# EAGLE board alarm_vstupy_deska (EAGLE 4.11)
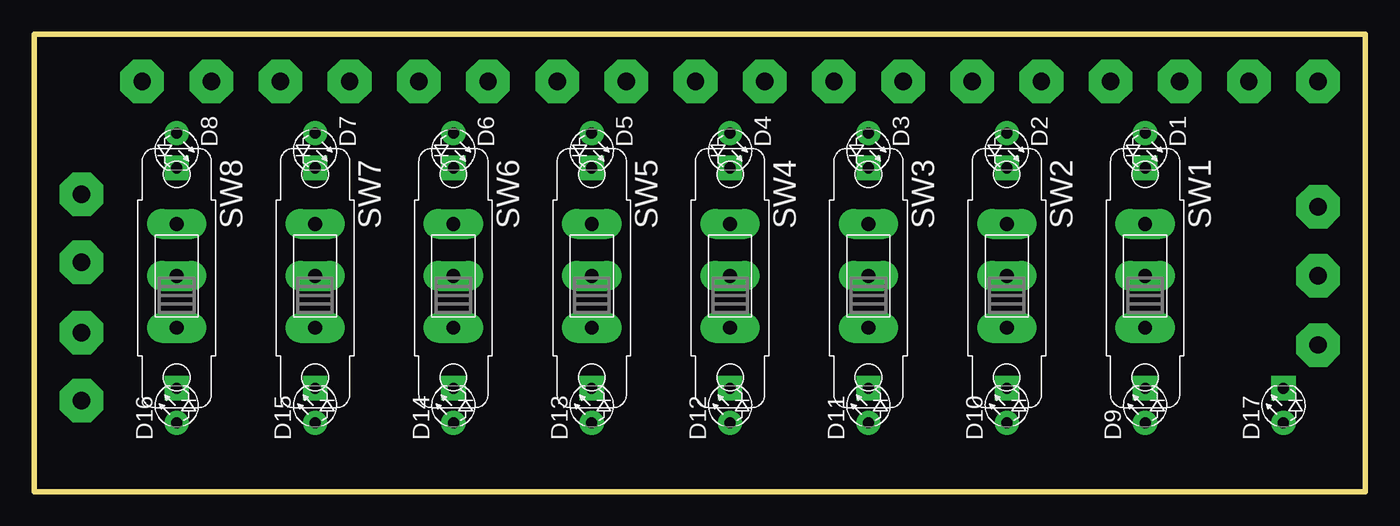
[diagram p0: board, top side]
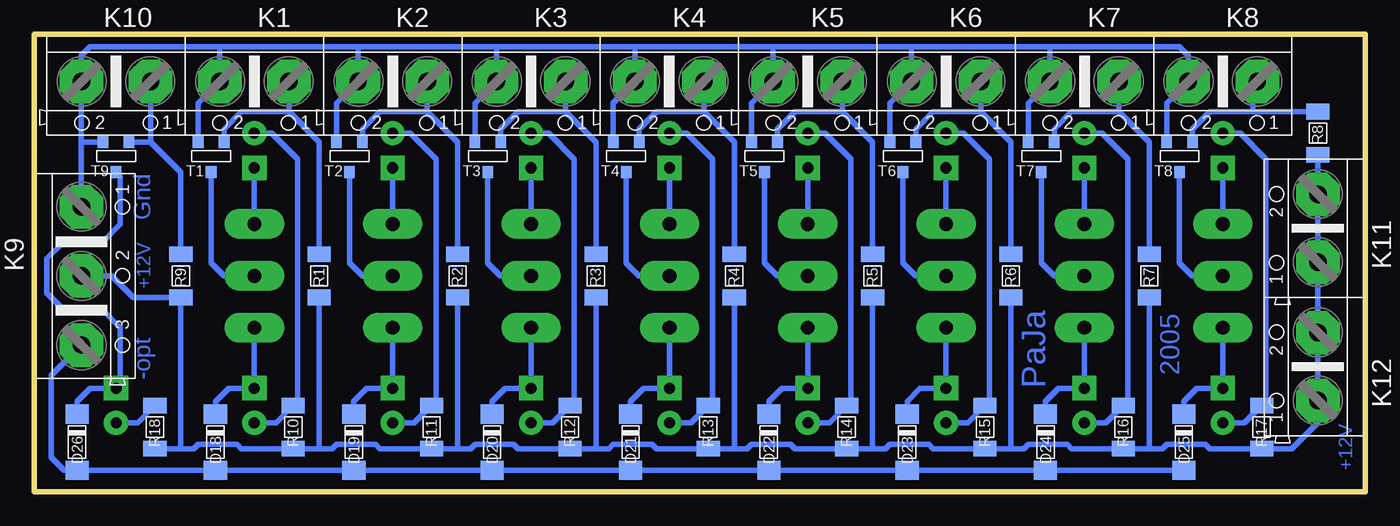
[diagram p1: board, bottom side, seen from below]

Size 97.78 x 33.65 mm. Coordinates in mm from the lower left corner, seen from the top.
Outline: 0,0 97.78,0 97.78,33.65 0,33.65 0,0
Copper layers (1*16): Top 0.035mm / dielectric 1.5mm / Bottom 0.035mm
Design rules "default": minimum track width 10mil, minimum drill 24mil, track to track 8mil, track to pad 8mil, pad to pad 8mil, via to via 8mil, smd to smd 8mil, copper to edge 40mil, drill to drill 8mil, minimum pad ring 10mil, minimum via ring 8mil, stop-mask expansion 4mil, vias tented up to drill 0mil, thermal gap 10mil

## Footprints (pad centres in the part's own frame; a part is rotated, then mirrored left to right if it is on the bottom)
LED_3 = drill 0.813 pad 1.778 round: A -1.27,0 | drill 0.813 pad 1.778 square: K 1.27,0
SOD-80 = smd 1.397 x 1.702: A 1.905,0; K -2.223,0
ARK500/2 = drill 1.27 pad 3.2 octagon: 1 -2.54,0; 2 2.54,0
ARK500/3 = drill 1.27 pad 3.2 octagon: 1 -5.08,0; 2 0,0; 3 5.08,0
ARK500/2' = drill 1.27 pad 3.2 octagon: 1 -2.5,0; 2 2.5,0
1206 = smd 1.143 x 1.702: 1 -1.587,0; 2 1.587,0
P-B144 = drill 1.016 pad 2.184 long: 1 -3.81,0; 2 0,0; 3 3.81,0
SOT-23 = smd 0.787 x 0.889: 1 0.953,-0.953; 2 -0.953,-0.953; 3 0,1.27

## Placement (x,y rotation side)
D1  zel  [LED_3]  81.6,25.08 270 top
D2  zel  [LED_3]  71.44,25.08 270 top
D3  zel  [LED_3]  61.28,25.08 270 top
D4  zel  [LED_3]  51.12,25.08 270 top
D5  zel  [LED_3]  40.96,25.08 270 top
D6  zel  [LED_3]  30.8,25.08 270 top
D7  zel  [LED_3]  20.64,25.08 270 top
D8  zel  [LED_3]  10.48,25.08 270 top
D9  cer  [LED_3]  81.6,6.35 90 top
D10  cer  [LED_3]  71.44,6.35 90 top
D11  cer  [LED_3]  61.28,6.35 90 top
D12  cer  [LED_3]  51.12,6.35 90 top
D13  cer  [LED_3]  40.96,6.35 90 top
D14  cer  [LED_3]  30.8,6.35 90 top
D15  cer  [LED_3]  20.64,6.35 90 top
D16  cer  [LED_3]  10.48,6.35 90 top
D17  cer  [LED_3]  91.76,6.35 90 top
D18  1N4148  [SOD-80]  84.45,3.49 270 bottom
D19  1N4148  [SOD-80]  74.29,3.49 270 bottom
D20  1N4148  [SOD-80]  64.13,3.49 270 bottom
D21  1N4148  [SOD-80]  53.98,3.49 270 bottom
D22  1N4148  [SOD-80]  43.81,3.49 270 bottom
D23  1N4148  [SOD-80]  33.66,3.49 270 bottom
D24  1N4148  [SOD-80]  23.5,3.49 270 bottom
D25  1N4148  [SOD-80]  13.34,3.49 270 bottom
D26  1N4148  [SOD-80]  94.61,3.49 270 bottom
K1  in1  [ARK500/2]  81.6,30.16 180 bottom
K2  in1  [ARK500/2]  71.44,30.16 180 bottom
K3  in1  [ARK500/2]  61.28,30.16 180 bottom
K4  in1  [ARK500/2]  51.12,30.16 180 bottom
K5  in1  [ARK500/2]  40.96,30.16 180 bottom
K6  in1  [ARK500/2]  30.8,30.16 180 bottom
K7  in1  [ARK500/2]  20.64,30.16 180 bottom
K8  in1  [ARK500/2]  10.48,30.16 180 bottom
K9  ARK500/3  [ARK500/3]  94.3,15.88 270 bottom
K10  TAMPER  [ARK500/2]  91.76,30.16 180 bottom
K11  [ARK500/2']  3.49,19.37 90 bottom
K12  [ARK500/2']  3.49,9.21 90 bottom
R1  33k  [1206]  76.83,15.88 270 bottom
R2  33k  [1206]  66.67,15.88 270 bottom
R3  33k  [1206]  56.52,15.88 270 bottom
R4  33k  [1206]  46.36,15.88 270 bottom
R5  33k  [1206]  36.2,15.88 270 bottom
R6  33k  [1206]  26.04,15.88 270 bottom
R7  33k  [1206]  15.88,15.88 270 bottom
R8  33k  [1206]  3.49,26.35 270 bottom
R9  33k  [1206]  86.99,15.88 270 bottom
R10  1k  [1206]  78.74,4.76 270 bottom
R11  1k  [1206]  68.58,4.76 270 bottom
R12  1k  [1206]  58.42,4.76 270 bottom
R13  1k  [1206]  48.26,4.76 270 bottom
R14  1k  [1206]  38.1,4.76 270 bottom
R15  1k  [1206]  27.94,4.76 270 bottom
R16  1k  [1206]  17.78,4.76 270 bottom
R17  1k  [1206]  7.62,4.76 270 bottom
R18  1k  [1206]  88.9,4.76 270 bottom
SW1  P-B144  [P-B144]  81.6,15.88 270 top
SW2  P-B144  [P-B144]  71.44,15.88 270 top
SW3  P-B144  [P-B144]  61.28,15.88 270 top
SW4  P-B144  [P-B144]  51.12,15.88 270 top
SW5  P-B144  [P-B144]  40.96,15.88 270 top
SW6  P-B144  [P-B144]  30.8,15.88 270 top
SW7  P-B144  [P-B144]  20.64,15.88 270 top
SW8  P-B144  [P-B144]  10.48,15.88 270 top
T1  BC846  [SOT-23]  84.77,24.77 180 bottom
T2  BC846  [SOT-23]  74.61,24.77 180 bottom
T3  BC846  [SOT-23]  64.45,24.77 180 bottom
T4  BC846  [SOT-23]  54.29,24.77 180 bottom
T5  BC846  [SOT-23]  44.13,24.77 180 bottom
T6  BC846  [SOT-23]  33.97,24.77 180 bottom
T7  BC846  [SOT-23]  23.81,24.77 180 bottom
T8  BC846  [SOT-23]  13.65,24.77 180 bottom
T9  BC846  [SOT-23]  91.76,24.77 180 bottom

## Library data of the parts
D1-D26 R1-R18 = #PaJa_13
K1-K10 SW1-SW8 T1-T9 = #PaJa_14
K11 K12 = #PaJa_15

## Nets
+12V: K9.2 K11.1 K11.2 K12.1 K12.2 R1.2 R2.2 R3.2 R4.2 R5.2 R6.2 R7.2 R8.2 R9.2 R10.2 R11.2 R12.2 R13.2 R14.2 R15.2 R16.2 R17.2 R18.2
ALARM: D18.A D19.A D20.A D21.A D22.A D23.A D24.A D25.A D26.A K9.3
GND: K1.2 K2.2 K3.2 K4.2 K5.2 K6.2 K7.2 K8.2 K9.1 K10.2 T1.1 T2.1 T3.1 T4.1 T5.1 T6.1 T7.1 T8.1 T9.1
N$1: K1.1 R1.1 T1.2
N$2: SW1.2 T1.3
N$3: D1.A D9.A R10.1
N$4: D1.K SW1.1
N$5: D2.A D10.A R11.1
N$6: D9.K D18.K SW1.3
N$7: D2.K SW2.1
N$8: D10.K D19.K SW2.3
N$9: SW2.2 T2.3
N$10: K2.1 R2.1 T2.2
N$11: D3.A D11.A R12.1
N$12: D3.K SW3.1
N$13: D11.K D20.K SW3.3
N$14: SW3.2 T3.3
N$15: K3.1 R3.1 T3.2
N$16: D4.A D12.A R13.1
N$17: D4.K SW4.1
N$18: D12.K D21.K SW4.3
N$19: SW4.2 T4.3
N$20: K4.1 R4.1 T4.2
N$21: D5.A D13.A R14.1
N$22: D5.K SW5.1
N$23: D13.K D22.K SW5.3
N$24: SW5.2 T5.3
N$25: K5.1 R5.1 T5.2
N$26: D6.A D14.A R15.1
N$27: D6.K SW6.1
N$28: D14.K D23.K SW6.3
N$29: SW6.2 T6.3
N$30: K6.1 R6.1 T6.2
N$31: D7.A D15.A R16.1
N$32: D7.K SW7.1
N$33: D15.K D24.K SW7.3
N$34: SW7.2 T7.3
N$35: K7.1 R7.1 T7.2
N$36: D8.A D16.A R17.1
N$37: D8.K SW8.1
N$38: D16.K D25.K SW8.3
N$39: SW8.2 T8.3
N$40: K8.1 R8.1 T8.2
N$45: K10.1 R9.1 T9.2
S$1: D17.A R18.1
S$3: D17.K D26.K T9.3

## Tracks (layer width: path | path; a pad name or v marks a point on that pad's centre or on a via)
+12V
  Bottom 0.406: 76.83,3.17 R1.2 | 76.83,3.17 R10.2 82.55,3.17 82.87,3.49 85.72,3.49 86.04,3.17 86.99,3.17 | 76.83,3.17 75.88,3.17 75.56,3.49 72.71,3.49 72.39,3.17 R11.2 66.67,3.17 | 66.67,3.17 R2.2 | 66.67,3.17 65.72,3.17 65.4,3.49 62.55,3.49 62.23,3.17 R12.2 56.52,3.17 | 56.52,3.17 R3.2 | 56.52,3.17 55.56,3.17 55.24,3.49 52.39,3.49 52.07,3.17 R13.2 46.36,3.17 | 46.36,3.17 R4.2 | 46.36,3.17 45.4,3.17 45.09,3.49 42.23,3.49 41.91,3.17 R14.2 36.2,3.17 | 36.2,3.17 R5.2 | 36.2,3.17 35.24,3.17 34.93,3.49 32.07,3.49 31.75,3.17 R15.2 26.04,3.17 | 26.04,3.17 R6.2 | 26.04,3.17 25.08,3.17 24.77,3.49 21.91,3.49 21.59,3.17 R16.2 15.88,3.17 | 15.88,3.17 R7.2 | 15.88,3.17 14.92,3.17 14.61,3.49 11.75,3.49 11.43,3.17 R17.2 5.4,3.17 3.49,5.08 K12.1 K12.2 K11.1 K11.2 R8.2 | 86.99,3.17 R9.2 90.49,14.29 92.07,15.88 K9.2 | 86.99,3.17 R18.2
ALARM
  Bottom 0.406: 75.25,1.59 74.93,1.59 | 75.25,1.59 D18.A D26.A 95.57,1.59 96.52,2.54 96.52,8.57 K9.3 | 75.25,1.59 D19.A D20.A D21.A D22.A D23.A D24.A D25.A
GND
  Bottom 0.406: 84.14,32.7 K1.2 85.72,28.57 T1.1 | 73.98,32.7 84.14,32.7 | 73.98,32.7 K2.2 75.56,28.57 T2.1 | T3.1 65.4,28.57 K3.2 63.82,32.7 | T4.1 55.24,28.57 K4.2 53.66,32.7 | T5.1 45.09,28.57 K5.2 43.5,32.7 | T6.1 34.93,28.57 K6.2 33.34,32.7 | T8.1 14.61,28.57 K8.2 13.02,32.07 13.65,32.7 23.18,32.7 | T7.1 24.77,28.57 K7.2 23.18,32.7 | 23.18,32.7 33.34,32.7 | 33.34,32.7 43.5,32.7 | 43.5,32.7 53.66,32.7 | 53.66,32.7 63.82,32.7 | 63.82,32.7 73.98,32.7 | 84.14,32.7 93.66,32.7 94.3,32.07 K10.2 94.3,25.72 | 94.3,25.72 T9.1 | 94.3,25.72 K9.1
N$1
  Bottom 0.406: T1.2 83.82,26.67 82.55,27.94 79.06,27.94 | R1.1 76.83,25.72 79.06,27.94 | 79.06,27.94 K1.1
N$2
  Bottom 0.406: T1.3 84.77,16.83 83.82,15.88 SW1.2
N$3
  Bottom 0.406: D1.A 80.33,26.35 78.42,24.45 78.42,6.67 R10.1 80.01,5.08 D9.A
N$4
  Bottom 0.406: SW1.1 D1.K
N$5
  Bottom 0.406: D2.A 70.17,26.35 68.26,24.45 68.26,6.67 R11.1 69.85,5.08 D10.A
N$6
  Bottom 0.406: SW1.3 D9.K 83.5,7.62 84.45,6.67 D18.K
N$7
  Bottom 0.406: SW2.1 D2.K
N$8
  Bottom 0.406: SW2.3 D10.K 73.34,7.62 74.29,6.67 D19.K
N$9
  Bottom 0.406: T2.3 74.61,16.83 73.66,15.88 SW2.2
N$10
  Bottom 0.406: T2.2 73.66,26.67 72.39,27.94 68.9,27.94 | R2.1 66.67,25.72 68.9,27.94 | 68.9,27.94 K2.1
N$11
  Bottom 0.406: D3.A 60.01,26.35 58.1,24.45 58.1,6.67 R12.1 59.69,5.08 D11.A
N$12
  Bottom 0.406: SW3.1 D3.K
N$13
  Bottom 0.406: SW3.3 D11.K 63.18,7.62 64.13,6.67 D20.K
N$14
  Bottom 0.406: T3.3 64.45,16.83 63.5,15.88 SW3.2
N$15
  Bottom 0.406: T3.2 63.5,26.67 62.23,27.94 58.74,27.94 | R3.1 56.52,25.72 58.74,27.94 | 58.74,27.94 K3.1
N$16
  Bottom 0.406: D4.A 49.85,26.35 47.94,24.45 47.94,6.67 R13.1 49.53,5.08 D12.A
N$17
  Bottom 0.406: SW4.1 D4.K
N$18
  Bottom 0.406: SW4.3 D12.K 53.02,7.62 53.98,6.67 D21.K
N$19
  Bottom 0.406: T4.3 54.29,16.83 53.34,15.88 SW4.2
N$20
  Bottom 0.406: T4.2 53.34,26.67 52.07,27.94 48.58,27.94 | R4.1 46.36,25.72 48.58,27.94 | 48.58,27.94 K4.1
N$21
  Bottom 0.406: D5.A 39.69,26.35 37.78,24.45 37.78,6.67 R14.1 39.37,5.08 D13.A
N$22
  Bottom 0.406: SW5.1 D5.K
N$23
  Bottom 0.406: SW5.3 D13.K 42.86,7.62 43.81,6.67 D22.K
N$24
  Bottom 0.406: T5.3 44.13,16.83 43.18,15.88 SW5.2
N$25
  Bottom 0.406: T5.2 43.18,26.67 41.91,27.94 38.42,27.94 | R5.1 36.2,25.72 38.42,27.94 | 38.42,27.94 K5.1
N$26
  Bottom 0.406: D6.A 29.53,26.35 27.62,24.45 27.62,6.67 R15.1 29.21,5.08 D14.A
N$27
  Bottom 0.406: SW6.1 D6.K
N$28
  Bottom 0.406: SW6.3 D14.K 32.7,7.62 33.66,6.67 D23.K
N$29
  Bottom 0.406: T6.3 33.97,16.83 33.02,15.88 SW6.2
N$30
  Bottom 0.406: T6.2 33.02,26.67 31.75,27.94 28.26,27.94 | R6.1 26.04,25.72 28.26,27.94 | 28.26,27.94 K6.1
N$31
  Bottom 0.406: D7.A 19.37,26.35 17.46,24.45 17.46,6.67 R16.1 19.05,5.08 D15.A
N$32
  Bottom 0.406: SW7.1 D7.K
N$33
  Bottom 0.406: SW7.3 D15.K 22.54,7.62 23.5,6.67 D24.K
N$34
  Bottom 0.406: T7.3 23.81,16.83 22.86,15.88 SW7.2
N$35
  Bottom 0.406: T7.2 22.86,26.67 21.59,27.94 18.1,27.94 | R7.1 15.88,25.72 18.1,27.94 | 18.1,27.94 K7.1
N$36
  Bottom 0.406: D8.A 9.21,26.35 7.3,24.45 7.3,6.67 R17.1 8.89,5.08 D16.A
N$37
  Bottom 0.406: SW8.1 D8.K
N$38
  Bottom 0.406: SW8.3 D16.K 12.38,7.62 13.34,6.67 D25.K
N$39
  Bottom 0.406: T8.3 13.65,16.83 12.7,15.88 SW8.2
N$40
  Bottom 0.406: T8.2 12.7,26.67 11.43,27.94 8.25,27.94 | R8.1 8.25,27.94 | K8.1 8.25,29.84 8.25,27.94
N$45
  Bottom 0.406: 89.22,25.72 T9.2 | 89.22,25.72 K10.1 | R9.1 86.99,23.5 89.22,25.72
S$1
  Bottom 0.406: R18.1 90.17,5.08 D17.A
S$3
  Bottom 0.406: T9.3 91.44,23.18 91.44,19.68 92.71,18.41 95.57,18.41 96.84,17.14 96.84,14.61 95.57,13.34 92.71,13.34 91.44,12.06 91.44,7.94 D17.K 93.66,7.62 94.61,6.67 D26.K

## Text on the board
Bottom: Gnd | +12V | 2005 | PaJa | -opt | +12V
